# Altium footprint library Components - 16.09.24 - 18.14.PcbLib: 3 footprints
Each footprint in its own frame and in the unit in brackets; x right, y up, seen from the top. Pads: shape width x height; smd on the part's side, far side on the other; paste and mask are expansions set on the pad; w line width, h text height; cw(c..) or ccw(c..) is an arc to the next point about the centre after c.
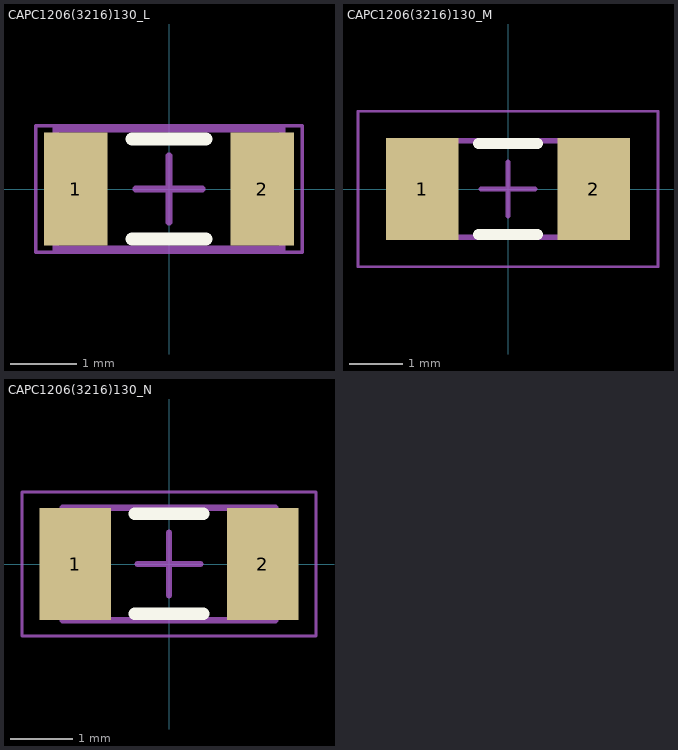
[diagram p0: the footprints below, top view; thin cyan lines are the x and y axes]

## CAPC1206(3216)130_L [mm] "Chip Capacitor, Body 3.2x1.6mm, Height 1.3mm, IPC High Density"
height 1.3
pads (2):
  rect 0.95x1.7 smd: 1(-1.4,0) 2(1.4,0)
Top Overlay:
  lines w0.2: -0.55,-0.75 0.55,-0.75 ; -0.55,0.75 0.55,0.75
Mechanical 13:
  lines w0.1: -1.7,-0.9 1.7,-0.9 1.7,0.9 -1.7,0.9 -1.7,-0.9
Mechanical 15:
  lines w0.05: -2,-0.95 2,-0.95 2,0.95 -2,0.95 -2,-0.95
  lines w0.1: -0.5,0 0.5,0 ; 0,-0.5 0,0.5
3D body: height 1.3, standoff 0, extent 1.2,-0.9 1.7,0.9
3D body: height 1.3, standoff 0, extent -1.7,-0.9 -1.2,0.9
3D body: height 1.3, standoff 0, extent -1.2,-0.9 1.2,0.9

## CAPC1206(3216)130_M [mm] "Chip Capacitor, Body 3.2x1.6mm, Height 1.3mm, IPC Low Density"
height 1.3
pads (2):
  rect 1.35x1.9 smd: 1(-1.6,0) 2(1.6,0)
Top Overlay:
  lines w0.2: -0.55,-0.85 0.55,-0.85 ; -0.55,0.85 0.55,0.85
Mechanical 13:
  lines w0.1: -1.7,-0.9 1.7,-0.9 1.7,0.9 -1.7,0.9 -1.7,-0.9
Mechanical 15:
  lines w0.05: -2.8,-1.45 2.8,-1.45 2.8,1.45 -2.8,1.45 -2.8,-1.45
  lines w0.1: -0.5,0 0.5,0 ; 0,-0.5 0,0.5
3D body: height 1.3, standoff 0, extent 1.2,-0.9 1.7,0.9
3D body: height 1.3, standoff 0, extent -1.7,-0.9 -1.2,0.9
3D body: height 1.3, standoff 0, extent -1.2,-0.9 1.2,0.9

## CAPC1206(3216)130_N [mm] "Chip Capacitor, Body 3.2x1.6mm, Height 1.3mm, IPC Medium Density"
height 1.3
pads (2):
  rect 1.15x1.8 smd: 1(-1.5,0) 2(1.5,0)
Top Overlay:
  lines w0.2: -0.55,-0.8 0.55,-0.8 ; -0.55,0.8 0.55,0.8
Mechanical 13:
  lines w0.1: -1.7,-0.9 1.7,-0.9 1.7,0.9 -1.7,0.9 -1.7,-0.9
Mechanical 15:
  lines w0.05: -2.35,-1.15 2.35,-1.15 2.35,1.15 -2.35,1.15 -2.35,-1.15
  lines w0.1: -0.5,0 0.5,0 ; 0,-0.5 0,0.5
3D body: height 1.3, standoff 0, extent 1.2,-0.9 1.7,0.9
3D body: height 1.3, standoff 0, extent -1.7,-0.9 -1.2,0.9
3D body: height 1.3, standoff 0, extent -1.2,-0.9 1.2,0.9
